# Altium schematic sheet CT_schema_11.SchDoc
size 274 x 160 mm
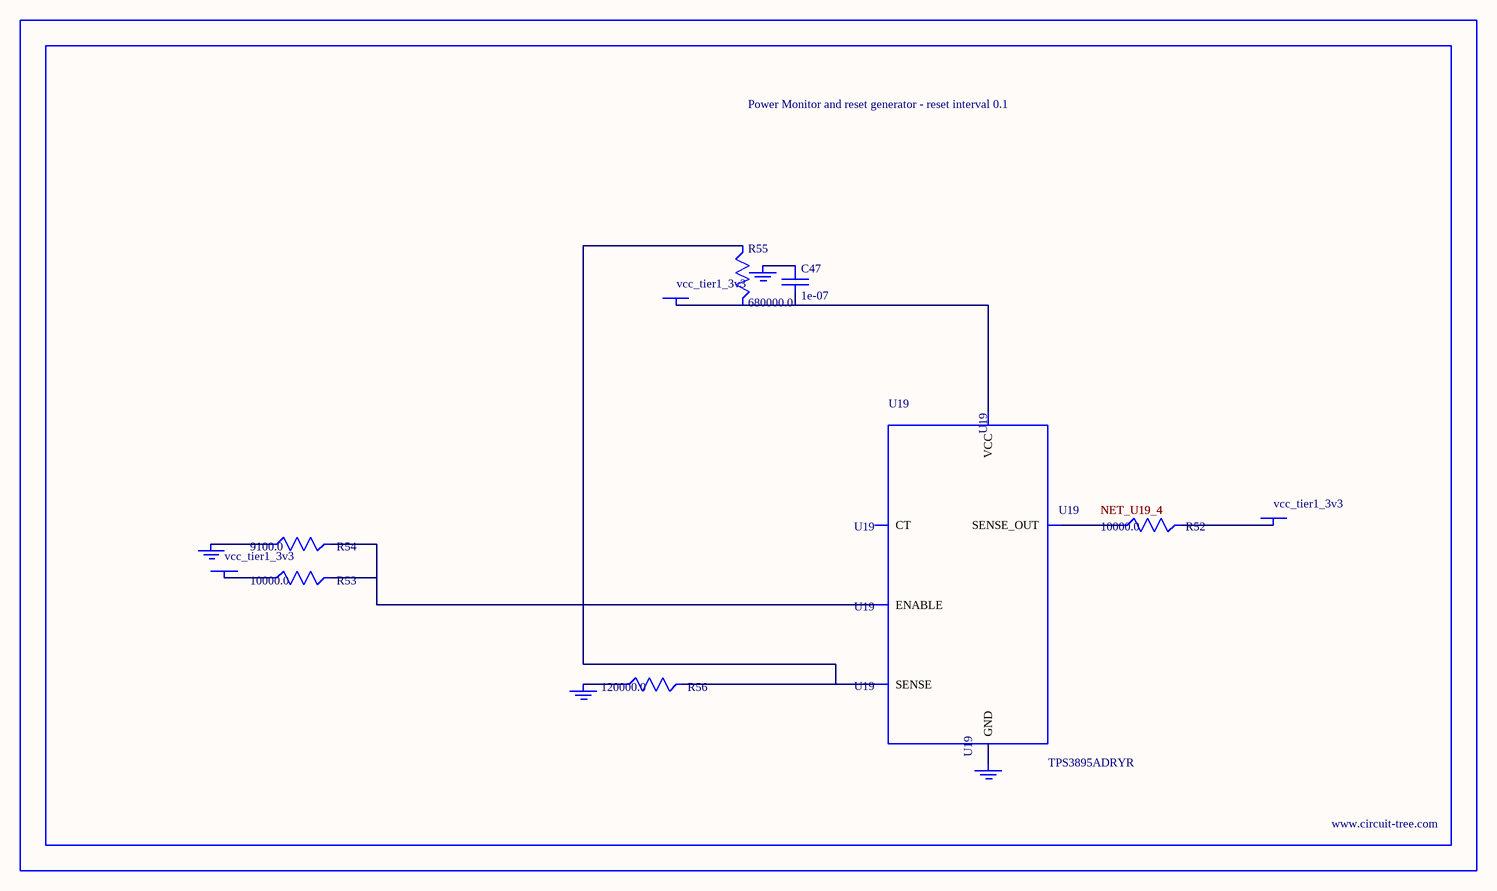
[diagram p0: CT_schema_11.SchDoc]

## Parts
BORDER10  (no value)
C47  1e-07  [C0402]
GND_INSTANCE_10_0  (no value)
GND_INSTANCE_10_1  (no value)
GND_INSTANCE_10_2  (no value)
GND_INSTANCE_10_3  (no value)
POWER_INSTANCE_10_0  vcc_tier1_3v3
POWER_INSTANCE_10_1  vcc_tier1_3v3
POWER_INSTANCE_10_2  vcc_tier1_3v3
R52  10000.0  [R0603]
R53  10000.0  [R0603]
R54  9100.0  [R0603]
R55  680000.0  [R0603]
R56  120000.0  [R0603]
U19  TPS3895ADRYR  [SON-6]

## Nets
NetC47_1: C47.1 GND_INSTANCE_10_2.0(GND)
NetC47_2: C47.2 POWER_INSTANCE_10_2.0(PWR) R55.2 U19.6(VCC)
NetGND_INSTANCE_10_0_0: GND_INSTANCE_10_0.0(GND) R54.1
NetGND_INSTANCE_10_1_0: GND_INSTANCE_10_1.0(GND) R56.1
NetGND_INSTANCE_10_3_0: GND_INSTANCE_10_3.0(GND) U19.2(GND)
NetPOWER_INSTANCE_10_0_0: POWER_INSTANCE_10_0.0(PWR) R53.1
NetPOWER_INSTANCE_10_1_0: POWER_INSTANCE_10_1.0(PWR) R52.2
NetR52_1: R52.1 U19.4(SENSE_OUT)
NetR53_2: R53.2 R54.2 U19.1(ENABLE)
NetR55_1: R55.1 R56.2 U19.3(SENSE)

Not connected (* = marked no-connect by the designer): U19 5(CT)

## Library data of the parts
BORDER10 = BORDER_PAGE10
C47 = C0402C104K3RACTU
GND_INSTANCE_10_0-GND_INSTANCE_10_3 = GND
POWER_INSTANCE_10_0-POWER_INSTANCE_10_2 = PWR
R52 R53 = RC0603JR-0710KL
R54 = RC0603JR-079K1L
R55 = RC0603JR-07680KL
R56 = RC0603JR-07120KL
